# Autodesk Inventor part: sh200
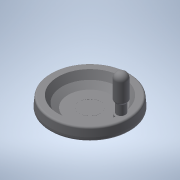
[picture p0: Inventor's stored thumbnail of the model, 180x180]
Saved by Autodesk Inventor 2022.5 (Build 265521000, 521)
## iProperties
Created: 2016-12
Part Number: sh200
Material: 一般
Document SubType Name: Modeling
Designer: imaocorp
Density: 1 g/cm^3
Appearance: 既定
Author: imaocorp
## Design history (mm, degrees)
node "sh200.x_t1"
node "sh200"
node "Base1"
